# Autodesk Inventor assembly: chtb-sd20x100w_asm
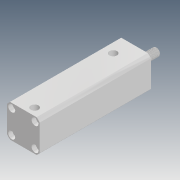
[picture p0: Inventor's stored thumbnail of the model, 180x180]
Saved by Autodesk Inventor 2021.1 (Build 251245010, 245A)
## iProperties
Company: Microsoft
Created: 2018-05
Part Number: chtb-sd20x100w_asm
Description: STEP AP214
Document SubType Name: Assembly
Designer: user
Title: chtb-sd20x100w_asm.STEP
Author: Windows
Revision Number: ÈÎºÎ
Sending System: SolidWorks 2015
Preprocessor: SwSTEP 2.0
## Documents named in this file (4)
- D:\Vault_2016\Projekty\Clamptek\Hydraulic\CHTB\CHTB-20\Inventor\CHTB-SD20x100W\chtb-sd20x100w_asm.iam
- D:\Vault_2016\Projekty\Clamptek\Hydraulic\CHTB\CHTB-20\Inventor\CHTB-SD20x100W\CHTB-SD20X100NBT.ipt
- D:\Vault_2016\Projekty\Clamptek\Hydraulic\CHTB\CHTB-20\Inventor\CHTB-SD20x100W\CHTB-SD20X100WHSG.ipt
- D:\Vault_2016\Projekty\Clamptek\Hydraulic\CHTB\CHTB-20\Inventor\CHTB-SD20x100W\QG.ipt
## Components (3 placed, 3 different names)
1. CHTB-SD20X100NBT_1
2. CHTB-SD20X100WHSG_2
3. QG_3
